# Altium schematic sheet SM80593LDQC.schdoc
size 127 x 101 mm
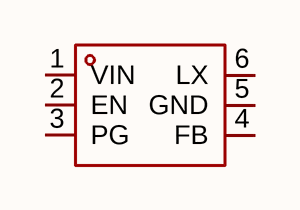
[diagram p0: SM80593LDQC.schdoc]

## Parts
U?  sm80593ldqc  [DFN-6_L1.5-W1.5-P0.50-BL]  (value not drawn)

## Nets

Not connected (* = marked no-connect by the designer): U? 1(VIN) 2(EN) 3(PG) 4(FB) 5(GND) 6(LX)

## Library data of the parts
U? = sm80593ldqc: 功能类型:降压型;工作电压:2.5V~5.5V;输出电压:-;输出电流:3A;输出类型:可调;; Manufacturer: Silergy(矽力杰); AddInBom: yes; ModelId: 74a233c6768b4d48ae7baff1158593b1; ModelName: DNF-6_L1.5-W1.5-H0.5-P0.50; ModelTransform: 59.8424,59.055,0,90,0,0,-0.16,-0.235,0; Function: 降压型; Output Current: 3A; Frequency - Switching: 1MHz; Synchronous Rectifier: 是; Number of Outputs: 1; Topology: 降压式; Quiescent Current: 55uA; Switch tube (built-in/external): 内置; Output Type: 可调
